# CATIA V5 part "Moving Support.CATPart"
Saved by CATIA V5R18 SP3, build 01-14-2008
Part number: Moving Part Support
Bounding box of the stored display mesh (mm): x 0 to 18, y -32.5 to 32.5, z -32.5 to 32.5
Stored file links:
  E:\#00 CATIA V5 Movie\#03 CATIA V5 Data\#07 KIN\Balance Unit (1)\Moving Support.CATPart
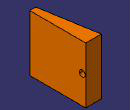
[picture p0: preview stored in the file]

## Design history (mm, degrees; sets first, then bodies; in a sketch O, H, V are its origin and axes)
Body1 (main body)
  Sketch1 on yz-plane, origin (0, 0, 0), H (0, 1, 0), V (0, 0, 1)
    line L1 (32.5, 32.5) -> (32.5, -32.5)
    line L2 (32.5, -32.5) -> (-32.5, -32.5)
    line L3 (-32.5, -32.5) -> (-32.5, 32.5)
    line L4 (-32.5, 32.5) -> (32.5, 32.5)
    length L4 = 65
    length L1 = 65
    vertical: L1 V, L3 V
    horizontal: L2 H, L4 H
    equidistance: L1 L3 O, L2 L4 O
  Pad1: profile Sketch1, direction (1, 0, 0), length 18
  Sketch2 on xy-plane, origin (0, 0, 0), H (1, 0, 0), V (0, 1, 0)
    point P1 (0, 32.5)
    line L1 (0, 32.5) -> (11, -32.5)
    line L2 (11, -32.5) -> (0, -32.5)
    line L3 (0, -32.5) -> (0, 32.5)
    reference projected point E1 (0, 32.5) from edge [start face of Pad1 | face of Pad1 from Sketch1.L1]
    reference projected line E2 (0, 32.5) -> (0, -32.5) from edge [start face of Pad1 | face of Pad1 from Sketch1.L4]
    reference projected line E3 (0, -32.5) -> (18, -32.5) from edge [face of Pad1 from Sketch1.L3 | face of Pad1 from Sketch1.L4]
    length L2 = 11
    coincidence: P1 V, P1 E1, L3 E2, L2 E3
    horizontal: L2 H
  Pocket1: profile Sketch2, direction (0, 0, -1), through (limit type 6), opposite side through (limit type 6)
  Sketch3 on face of Pocket1 from Sketch2.L1, origin (1.1754, 25.5544, 0), H (0.1669, -0.986, 0), V (0, 0, 1)
    point P1 (0, 0)
    reference projected point E1 (0, 0) from Sketch4.P4
    coincidence: E1 P1
  Hole1: placed by Sketch3, at (1.1754, 25.5544, 0) direction (0.986, 0.1669, 0), diameter 6.917, through (limit type 6), threaded "M8", thread diameter 8, thread depth 10, pitch 1
  Sketch4 on face of Pocket1 from Sketch2.L1, origin (5.3469, 0.9049, 0), H (0.1669, -0.986, 0), V (0, 0, 1)
    construction circle A1 centre (0, 0) radius 25
    point P1 (25, 0)
    point P2 (0, -25)
    point P3 (0, 25)
    point P4 (-25, 0)
    radius A1 = 25
    coincidence: P1 A1, P1 H, P2 A1, P2 V, P3 A1, P3 V, P4 A1, P4 H
  UserPattern1: of Hole1, copies 4, at the points of Sketch4
  Sketch5 on end face of Pad1, origin (18, 22.1493, 25.0346), H (0, 1, 0), V (0, 0, 1)
    point P1 (0.3507, -2.5346)
    reference projected line E1 (10.3507, 7.4654) -> (-54.6493, 7.4654) from edge [face of Pad1 from Sketch1.L4 | end face of Pad1]
    reference projected line E2 (10.3507, -57.5346) -> (10.3507, 7.4654) from edge [face of Pad1 from Sketch1.L1 | end face of Pad1]
    distance P1 E1 = 10
    distance P1 E2 = 10
  Hole2: placed by Sketch5, at (18, 22.5, 22.5) direction (-1, 0, 0), diameter 6.917, through (limit type 6), threaded "M8", thread diameter 8, thread depth 10, pitch 1
  RectPattern1: of Hole2, direction 1 instances 2, spacing 45, along edge [face of Pad1 from Sketch1.L4 | end face of Pad1], direction 2 instances 2, spacing 45, along edge [face of Pad1 from Sketch1.L3 | end face of Pad1]
Current feature: Hole1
